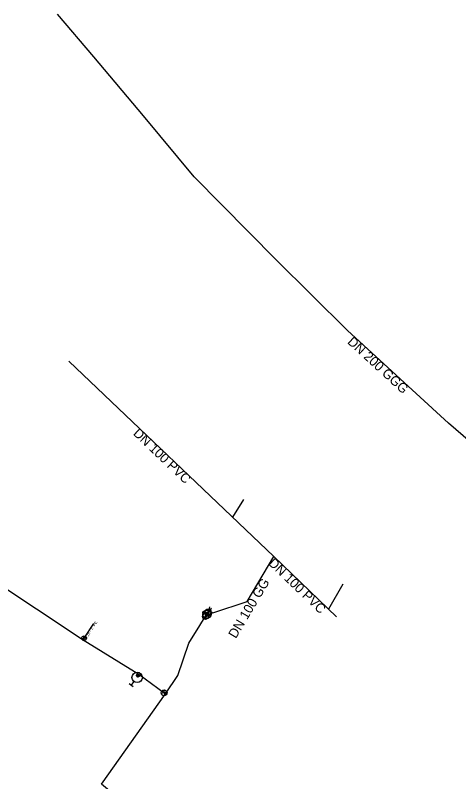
# Model space of a CAD drawing. Extents: x -443519 to -443021, y -1121477 to -1120870.
# Drawn here: x -443256.5 to -443181.7, y -1121307.3 to -1121178.2 of the extents above; entities that cross this region are included whole.
import ezdxf

# ---------------------------------------------------------------- set-up
doc = ezdxf.new("R2010")
doc.units = 0
for name, color, linetype in [('_hydrantova_odbocka_', 7, 'Continuous'), ('_kalosvod_', 7, 'Continuous'), ('_pripojka_priblizne_', 7, 'Continuous'), ('_voda_smvak_prevzato_z_dokumentace_', 7, 'Continuous'), ('_voda_smvak_priblizne_', 7, 'Continuous'), ('Default', 7, 'Continuous'), ('MoLevel 2', 7, 'Continuous'), ('MoLevel 27', 7, 'Continuous'), ('MoLevel 28', 7, 'Continuous'), ('MoLevel 30', 7, 'Continuous'), ('MoLevel 32', 7, 'Continuous'), ('MoLevel 42', 7, 'Continuous'), ('MoLevel 46', 7, 'Continuous'), ('MoLevel 53', 7, 'Continuous')]:
    doc.layers.add(name, color=color, linetype=linetype)

# ---------------------------------------------------------------- blocks, each defined once
blk = doc.blocks.new('_uzaver_')
at = {"layer": 'Default'}
for p, q in [((-0.000035, -0.000035), (0.000035, 0.000035)), ((0.000035, -0.000035), (-0.000035, 0.000035))]:
    blk.add_line(p, q, dxfattribs=at)
for radius in [0.00005, 0.0000025]:
    blk.add_circle((0, 0), radius, dxfattribs=at)
blk = doc.blocks.new('_uzaver_pripojka_')
at = {"layer": 'Default'}
for p, q in [((-0.000035, -0.000035), (0.000035, 0.000035)), ((0.000035, -0.000035), (-0.000035, 0.000035))]:
    blk.add_line(p, q, dxfattribs=at)
for radius in [0.00005, 0.0000025]:
    blk.add_circle((0, 0), radius, dxfattribs=at)
blk = doc.blocks.new('_hydrant_voda_')
at = {"layer": 'Default'}
for p, q in [((-0.0000225, 0.000095), (0.0000225, 0.000095)), ((0, 0.000095), (0, 0.00005))]:
    blk.add_line(p, q, dxfattribs=at)
blk.add_circle((0, 0), 0.00005, dxfattribs=at)
blk = doc.blocks.new('_sachta_voda_')
at = {"layer": 'Default'}
blk.add_lwpolyline([(-0.00001, 0.000065), (0, 0.000035), (0.00001, 0.000065)], dxfattribs=at)
blk.add_circle((0, 0), 0.000035, dxfattribs=at)
blk = doc.blocks.new('_poklop_voda_')
at = {"layer": 'Default'}
blk.add_lwpolyline([(-0.00002, 0.00002), (0.00002, 0.00002), (0.00002, -0.00002), (-0.00002, -0.00002), (-0.00002, 0.00002)], dxfattribs=at)

msp = doc.modelspace()

# ---------------------------------------------------------------- linework, layer by layer
at = {"layer": '_hydrantova_odbocka_'}
msp.add_lwpolyline([(-443235.62, -1121289.19), (-443235.78, -1121289.42), (-443235.92, -1121289.73)], dxfattribs=at)
at = {"layer": '_kalosvod_'}
msp.add_line((-443224.17, -1121279.08), (-443223.89, -1121279.25), dxfattribs=at)
at = {"layer": '_pripojka_priblizne_'}
for p, q in [((-443217.99, -1121259.76), (-443219.87, -1121262.71)), ((-443201.23, -1121274), (-443203.67, -1121278.22))]:
    msp.add_line(p, q, dxfattribs=at)
msp.add_lwpolyline([(-443245.04, -1121283.38), (-443244.88, -1121283.13), (-443243.25, -1121280.64)], dxfattribs=at)
at = {"layer": '_voda_smvak_prevzato_z_dokumentace_'}
for p, q in [((-443247.44, -1121236.46), (-443212.87, -1121269.38)), ((-443224.6, -1121278.82), (-443224.17, -1121279.08)), ((-443224.41, -1121279.46), (-443224.17, -1121279.08)), ((-443224.17, -1121279.08), (-443223.96, -1121278.72)), ((-443223.89, -1121279.25), (-443224.17, -1121279.08)), ((-443223.96, -1121278.72), (-443223.9, -1121278.62)), ((-443225.36, -1121280.99), (-443224.55, -1121279.69)), ((-443224.55, -1121279.69), (-443224.41, -1121279.46)), ((-443235.62, -1121289.19), (-443231.38, -1121292.32)), ((-443231.38, -1121292.32), (-443231.14, -1121292.5))]:
    msp.add_line(p, q, dxfattribs=at)
for points in [[(-443027.13, -1121379.47), (-443028.32, -1121378.44), (-443040.91, -1121368.14), (-443043.34, -1121366.14), (-443054.07, -1121355.17), (-443056.37, -1121349.71), (-443076.63, -1121333.69), (-443087.9, -1121325.51), (-443098.89, -1121316.36), (-443115.85, -1121301.92), (-443117.14, -1121299.83), (-443127.63, -1121293.04), (-443137.86, -1121284.27), (-443144.91, -1121279.74), (-443163.69, -1121263.91), (-443183.42, -1121246.92), (-443200.48, -1121231.27), (-443212.46, -1121219.38), (-443226.3, -1121205.42), (-443234.86, -1121195.13), (-443243.22, -1121185.2), (-443249.33, -1121177.99)], [(-443310.84, -1121239.43), (-443294.2, -1121251.61), (-443268.86, -1121267.6), (-443245.04, -1121283.38), (-443235.62, -1121289.19)], [(-443223.9, -1121278.62), (-443223.8, -1121278.45), (-443223.17, -1121278.85), (-443217.38, -1121276.95), (-443212.87, -1121269.38)], [(-443231.14, -1121292.5), (-443229.06, -1121289.4), (-443227.19, -1121283.97), (-443225.36, -1121280.99)], [(-443225.51, -1121324.29), (-443225.66, -1121321.35), (-443241.94, -1121307.71), (-443231.14, -1121292.5)]]:
    msp.add_lwpolyline(points, dxfattribs=at)
at = {"layer": '_voda_smvak_priblizne_'}
msp.add_line((-443212.87, -1121269.38), (-443202.33, -1121279.5), dxfattribs=at)

# ---------------------------------------------------------------- block references
at = {"layer": 'MoLevel 27'}
for p, xscale, yscale, rotation in [((-443223.96, -1121278.72), 9999.999999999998, 10000.000000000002, -121.653786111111), ((-443224.41, -1121279.46), 9999.999999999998, 10000.000000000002, -121.653786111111), ((-443224.6, -1121278.82), 4999.999999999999, 5000, -31.17982222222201), ((-443223.89, -1121279.25), 4999.999999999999, 5000.000000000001, 148.91827014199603), ((-443235.78, -1121289.42), 5000, 5000.000000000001, 56.415838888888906), ((-443231.38, -1121292.32), 10000, 10000, 146.337613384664)]:
    msp.add_blockref('_uzaver_', p, dxfattribs=dict(at, xscale=xscale, yscale=yscale, rotation=rotation))
at = {"layer": 'MoLevel 28', "xscale": 17636.68430335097, "yscale": 17636.684303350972, "rotation": 142.933463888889}
msp.add_blockref('_hydrant_voda_', (-443235.92, -1121289.73), dxfattribs=at)
at = {"layer": 'MoLevel 30', "xscale": 20000, "yscale": 20000, "rotation": -28.922894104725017}
msp.add_blockref('_sachta_voda_', (-443224.17, -1121279.08), dxfattribs=at)
at = {"layer": 'MoLevel 42', "xscale": 10000, "yscale": 10000.000000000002, "rotation": 58.36396399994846}
msp.add_blockref('_poklop_voda_', (-443224.05, -1121279.14), dxfattribs=at)
at = {"layer": 'MoLevel 53', "xscale": 8000, "yscale": 8000, "rotation": 57.2388829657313}
msp.add_blockref('_uzaver_pripojka_', (-443244.88, -1121283.13), dxfattribs=at)

# ---------------------------------------------------------------- texts
at = {"layer": 'MoLevel 2'}
msp.add_text('DN 100 PVC', height=1.605, rotation=316.1456, dxfattribs=at).set_placement((-443213.91, -1121270.61))
at = {"layer": 'MoLevel 32'}
msp.add_text("DN 25 - 1'' PE", height=0.455, rotation=56.8772, dxfattribs=at).set_placement((-443244.75, -1121283.76))
at = {"layer": 'MoLevel 46'}
for s, rotation, p in [('DN 200 GGG', 317.4683, (-443200.58, -1121233.35)), ('DN 100 PVC', 316.4004, (-443236.71, -1121248.75)), ('DN 100 GG', 59.1913, (-443219.28, -1121283.28))]:
    msp.add_text(s, height=1.605, rotation=rotation, dxfattribs=at).set_placement(p)

doc.saveas('drawing.dxf')
